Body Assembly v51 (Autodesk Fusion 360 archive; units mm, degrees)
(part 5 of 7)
sketch "Sketch36" plane through (0, 0, 68.45) normal (0, 0, 1) x axis (-1, 0, 0)
  line L1 (-90.9149, 154.35) -> (-90.9149, 141.35)
  line L2 (-88.4149, 157.35) -> (-90.9149, 154.35)
  line L3 (-85.2649, 157.35) -> (-88.4149, 157.35)
  line L4 (-82.7649, 154.35) -> (-85.2649, 157.35)
  line L5 (-82.7649, 141.35) -> (-82.7649, 154.35)
  line L6 (-90.9149, 141.35) -> (-82.7649, 141.35)
  line L7 (-93.1899, 97.475) -> (-80.4899, 97.475)
  line L8 (-93.1899, 118.675) -> (-93.1899, 97.475)
  line L9 (-80.4899, 118.675) -> (-93.1899, 118.675)
  line L10 (-80.4899, 97.475) -> (-80.4899, 118.675)
  line L11 (-116.1, 79.5) -> (-116.1, 158.6)
  line L12 (31.35, 79.5) -> (-116.1, 79.5)
  line L13 (31.35, 158.6) -> (31.35, 79.5)
  line L14 (-84.35, 190.35) -> (-0.4, 190.35)
  line L15 (-93.9399, 38.65) -> (-79.7399, 38.65)
  line L16 (-93.9399, 61.85) -> (-93.9399, 38.65)
  line L17 (-79.7399, 61.85) -> (-93.9399, 61.85)
  line L18 (-79.7399, 38.65) -> (-79.7399, 61.85)
  line L19 (-116.1, 0.4) -> (-116.1, 79.5)
  line L20 (-0.4, -31.35) -> (-84.35, -31.35)
  line L21 (31.35, 79.5) -> (31.35, 0.4)
  line L22 (-116.1, 79.5) -> (31.35, 79.5)
  line L23 (-79.99, 14.95) -> (-84.65, 14.95)
  line L24 (-79.99, 4.05) -> (-79.99, 14.95)
  line L25 (-84.65, 4.05) -> (-79.99, 4.05)
  line L26 (-84.65, 14.95) -> (-84.65, 4.05)
  line L27 (-79.99, -8.05) -> (-84.65, -8.05)
  line L28 (-79.99, -18.95) -> (-79.99, -8.05)
  line L29 (-84.65, -18.95) -> (-79.99, -18.95)
  line L30 (-84.65, -8.05) -> (-84.65, -18.95)
  line L31 (-68.5771, 14.95) -> (-73.2371, 14.95)
  line L32 (-68.5771, 4.05) -> (-68.5771, 14.95)
  line L33 (-73.2371, 4.05) -> (-68.5771, 4.05)
  line L34 (-73.2371, 14.95) -> (-73.2371, 4.05)
  line L35 (-68.5771, -8.05) -> (-73.2371, -8.05)
  line L36 (-68.5771, -18.95) -> (-68.5771, -8.05)
  line L37 (-73.2371, -18.95) -> (-68.5771, -18.95)
  line L38 (-73.2371, -8.05) -> (-73.2371, -18.95)
  line L39 (-57.1643, 14.95) -> (-61.8243, 14.95)
  line L40 (-57.1643, 4.05) -> (-57.1643, 14.95)
  line L41 (-61.8243, 4.05) -> (-57.1643, 4.05)
  line L42 (-61.8243, 14.95) -> (-61.8243, 4.05)
  line L43 (-57.1643, -8.05) -> (-61.8243, -8.05)
  line L44 (-57.1643, -18.95) -> (-57.1643, -8.05)
  line L45 (-61.8243, -18.95) -> (-57.1643, -18.95)
  line L46 (-61.8243, -8.05) -> (-61.8243, -18.95)
  line L47 (-45.7514, 14.95) -> (-50.4114, 14.95)
  line L48 (-45.7514, 4.05) -> (-45.7514, 14.95)
  line L49 (-50.4114, 4.05) -> (-45.7514, 4.05)
  line L50 (-50.4114, 14.95) -> (-50.4114, 4.05)
  line L51 (-45.7514, -8.05) -> (-50.4114, -8.05)
  line L52 (-45.7514, -18.95) -> (-45.7514, -8.05)
  line L53 (-50.4114, -18.95) -> (-45.7514, -18.95)
  line L54 (-50.4114, -8.05) -> (-50.4114, -18.95)
  line L55 (-34.3386, 14.95) -> (-38.9986, 14.95)
  line L56 (-34.3386, 4.05) -> (-34.3386, 14.95)
  line L57 (-38.9986, 4.05) -> (-34.3386, 4.05)
  line L58 (-38.9986, 14.95) -> (-38.9986, 4.05)
  line L59 (-34.3386, -8.05) -> (-38.9986, -8.05)
  line L60 (-34.3386, -18.95) -> (-34.3386, -8.05)
  line L61 (-38.9986, -18.95) -> (-34.3386, -18.95)
  line L62 (-38.9986, -8.05) -> (-38.9986, -18.95)
  line L63 (-22.9257, 14.95) -> (-27.5857, 14.95)
  line L64 (-22.9257, 4.05) -> (-22.9257, 14.95)
  line L65 (-27.5857, 4.05) -> (-22.9257, 4.05)
  line L66 (-27.5857, 14.95) -> (-27.5857, 4.05)
  line L67 (-22.9257, -8.05) -> (-27.5857, -8.05)
  line L68 (-22.9257, -18.95) -> (-22.9257, -8.05)
  line L69 (-27.5857, -18.95) -> (-22.9257, -18.95)
  line L70 (-27.5857, -8.05) -> (-27.5857, -18.95)
  line L71 (-11.5129, 14.95) -> (-16.1729, 14.95)
  line L72 (-11.5129, 4.05) -> (-11.5129, 14.95)
  line L73 (-16.1729, 4.05) -> (-11.5129, 4.05)
  line L74 (-16.1729, 14.95) -> (-16.1729, 4.05)
  line L75 (-11.5129, -8.05) -> (-16.1729, -8.05)
  line L76 (-11.5129, -18.95) -> (-11.5129, -8.05)
  line L77 (-16.1729, -18.95) -> (-11.5129, -18.95)
  line L78 (-16.1729, -8.05) -> (-16.1729, -18.95)
  line L79 (-0.1, 14.95) -> (-4.76, 14.95)
  line L80 (-0.1, 4.05) -> (-0.1, 14.95)
  line L81 (-4.76, 4.05) -> (-0.1, 4.05)
  line L82 (-4.76, 14.95) -> (-4.76, 4.05)
  line L83 (-0.1, -8.05) -> (-4.76, -8.05)
  line L84 (-0.1, -18.95) -> (-0.1, -8.05)
  line L85 (-4.76, -18.95) -> (-0.1, -18.95)
  line L86 (-4.76, -8.05) -> (-4.76, -18.95)
  circle C1 centre (-113.9, 107.8) radius 1.7
  circle C2 centre (20.495, 179.495) radius 1.7
  circle C3 centre (-105.245, 179.495) radius 1.7
  circle C4 centre (29.15, 107.8) radius 1.7
  arc A1 centre (-0.4, 158.6) radius 31.75 clockwise from (-0.4, 190.35) to (31.35, 158.6)
  arc A2 centre (-84.35, 158.6) radius 31.75 clockwise from (-116.1, 158.6) to (-84.35, 190.35)
  circle C5 centre (-105.245, -20.495) radius 1.7
  circle C6 centre (29.15, 51.2) radius 1.7
  circle C7 centre (20.495, -20.495) radius 1.7
  circle C8 centre (-113.9, 51.2) radius 1.7
  arc A3 centre (-84.35, 0.4) radius 31.75 clockwise from (-84.35, -31.35) to (-116.1, 0.4)
  arc A4 centre (-0.4, 0.4) radius 31.75 clockwise from (31.35, 0.4) to (-0.4, -31.35)
extrude "Extrude1" cut sketch "Sketch36" profile of L7 L8 L9 L10 L15 L16 L17 L18 along normal blind 38.1
extrude "Extrude2" add of existing geometry blind 2.7432
extrude "Extrude53" new body of existing geometry blind 6.35
extrude "Extrude3" add of existing geometry blind 1.075
extrude "Extrude55" new body of existing geometry blind 6.35
extrude "Extrude57" add of existing geometry blind 22.86
extrude "Extrude56" add of existing geometry blind 15.24
combine "Combine3"
offset_faces "OffsetFaces1" distance -2
chamfer "Chamfer1" distance 3.175
extrude "Extrude4" add of existing geometry blind 6.35
extrude "Extrude5" add of existing geometry blind 6.35
extrude "Extrude6" add of existing geometry blind 15.4432
extrude "Extrude7" add of existing geometry blind 13.7668
extrude "Extrude8" add of existing geometry blind 13.7668
extrude "Extrude9" add of existing geometry blind 15.4432
extrude "Extrude10" cut of existing geometry blind -6.35
extrude "Extrude12" add of existing geometry blind 27.2288
extrude "Extrude13" add of existing geometry blind 25.5524
component_from_bodies "Body->Comp2"
copy_paste "CutPaste1"
copy_paste "CutPaste7"
sketch "Sketch37" plane through (-44.05, 0, 0) normal (-1, 0, 0) x axis (0, -1, 0)
  line L1 (158.5956, -1.65) -> (0.4044, -1.65)
  line L2 (158.5956, 62.1) -> (158.5956, -1.65)
  line L3 (0.4044, 62.1) -> (158.5956, 62.1)
  line L4 (0.4044, -1.65) -> (0.4044, 62.1)
  line L5 (153.8331, 3.1125) -> (5.1669, 3.1125)
  line L6 (153.8331, 57.3375) -> (153.8331, 3.1125)
  line L7 (5.1669, 57.3375) -> (153.8331, 57.3375)
  line L8 (5.1669, 3.1125) -> (5.1669, 57.3375)
  line L9 (109.775, 57.3375) -> (49.225, 57.3375)
  line L10 (109.775, 46.3849) -> (109.775, 57.3375)
  line L11 (49.225, 46.3849) -> (109.775, 46.3849)
  line L12 (49.225, 57.3375) -> (49.225, 46.3849)
  line L13 (109.775, 3.1125) -> (49.225, 3.1125)
  line L14 (109.775, 12.875) -> (109.775, 3.1125)
  line L15 (49.225, 12.875) -> (109.775, 12.875)
  line L16 (49.225, 3.1125) -> (49.225, 12.875)
  line L17 (44.4625, -1.65) -> (44.4625, 17.6375)
  line L18 (114.5375, -1.65) -> (44.4625, -1.65)
  line L19 (114.5375, 17.6375) -> (114.5375, -1.65)
  line L20 (44.4625, 17.6375) -> (114.5375, 17.6375)
  line L21 (44.4625, 62.1) -> (44.4625, 41.6224)
  line L22 (114.5375, 62.1) -> (44.4625, 62.1)
  line L23 (114.5375, 41.6224) -> (114.5375, 62.1)
  line L24 (44.4625, 41.6224) -> (114.5375, 41.6224)
  line L25 (5.1669, 41.6224) -> (44.4625, 41.6224)
  line L26 (5.1669, 17.6375) -> (44.4625, 17.6375)
  line L27 (79.5, -1.65) -> (79.5, 62.1)
  line L28 (44.4625, 17.6375) -> (44.4625, 41.6224)
  line L29 (5.1669, 41.6224) -> (44.4625, 17.6375)
  line L30 (79.5, 41.6224) -> (44.4625, 17.6375)
  line L31 (44.4625, 57.3375) -> (5.1669, 41.6224)
  line L32 (5.1669, 3.1125) -> (44.4625, 17.6375)
  circle C1 centre (50.925, 11.175) radius 1.7
  circle C2 centre (69.975, 48.0849) radius 1.7
  circle C3 centre (50.925, 48.0849) radius 1.7
  circle C4 centre (69.975, 11.175) radius 1.7
  circle C5 centre (89.025, 11.175) radius 1.7
  circle C6 centre (108.075, 48.0849) radius 1.7
  circle C7 centre (89.025, 48.0849) radius 1.7
  circle C8 centre (108.075, 11.175) radius 1.7
  circle C9 centre (50.925, 48.0849) radius 2.75
  circle C10 centre (108.075, 48.0849) radius 2.75
  circle C11 centre (108.075, 11.175) radius 2.75
  circle C12 centre (50.925, 11.175) radius 2.75
  circle C13 centre (44.4625, 3.1125) radius 8.55
  circle C14 centre (5.1669, 3.1125) radius 8.55
  circle C15 centre (44.4625, 57.3375) radius 8.55
  circle C16 centre (5.1669, 57.3375) radius 8.55
  point P18 (49.225, 57.3375)
  point P22 (49.225, 3.1125)
  point P38 (5.1669, 41.6224)
  point P39 (5.1669, 17.6375)
  point P40 (79.5, 62.1)
  point P41 (79.5, -1.65)
  point P42 (79.5, 41.6224)
  point P43 (44.4625, 57.3375)
  point P44 (44.4625, 3.1125)
  point P14 (5.1669, 3.1125)
  point P45 (5.1669, 3.1125)
  point P46 (44.4625, 57.3375)
  point P17 (5.1669, 57.3375)
  point P47 (5.1669, 57.3375)
  horizontal L9
  vertical L10
  horizontal L11
  vertical L12
  coincident L7 P18
  horizontal L13
  vertical L14
  horizontal L15
  vertical L16
  coincident L5 P22
  coincident L8 P38
  perpendicular L8 L25
  coincident L8 P39
  perpendicular L8 L26
  midpoint L3 P40
  midpoint L18 P41
  midpoint L24 P42
  coincident L21 P43
  coincident L7 P43
  coincident L17 P44
  coincident L5 P44
  coincident P14 P45
  coincident P43 P46
  coincident P17 P47
  tangent C3 L11
  tangent C3 L12
  tangent C1 L16
  tangent C1 L15
  tangent C8 L14
  tangent C6 L10
  dimension "d404" = -4.7625
  dimension "d405" = 4.7625
  dimension "d406" = -4.7625
  dimension "d409" diameter C15 = 17.1 (= "threadedinsertdiam + 0.5 in")
  dimension "d410" diameter C13 = 17.1 (= "d409")
  dimension "d411" diameter C14 = 17.1 (= "d409")
  dimension "d412" diameter C16 = 17.1 (= "d409")
split "Split3"
extrude "Extrude14" cut sketch "Sketch37" profile of L5 L7 L8 L17 L20 L21 L24 L25 L26 L27 L28 L29 L30 L31 L32 C13 C14 C15 C16 against normal blind 7.62
extrude "Extrude58" new body of existing geometry blind -2.3813 (= "( -0.1875 / 2 ) * 1 in")
extrude "Extrude60" add of existing geometry blind 30.48
combine "Combine4"
web "Web1" Thickness 4.7625
delete_face "DeleteFace4"
delete_face "DeleteFace5"
fillet "Fillet3" radius 1.5875 (= "( 1 / 16 ) * 1 in")
hole "Hole1" HoleDepth 10.0076 HoleDiameter 4.4 (= "threadedinsertdiam") TipAngle 180
extrude "Extrude15" add sketch "Sketch37" profile of L1 L3 L4 L18 L22 C13 C14 C15 C16 against normal blind 6.35
fillet "Fillet5" radius 6.35
mirror "Mirror1" mirrorStitchTolerance 0.1016
remove_body "RemoveBody6"
remove_body "RemoveBody7"
mirror "Mirror2" mirrorStitchTolerance 0.1016
sketch "Sketch38" plane through (128.8, 0, 0) normal (1, 0, 0) x axis (0, 1, 0)
  line L1 (-25.9568, 62.1) -> (-131.375, 62.1)
  line L2 (-25.9568, 64.7303) -> (-25.9568, 62.1)
  line L3 (-131.375, 64.7303) -> (-25.9568, 64.7303)
  line L4 (-131.375, 62.1) -> (-131.375, 64.7303)
  line L5 (-140.5403, 36.2986) -> (-119.3333, 23.3545)
  line L6 (-118.5063, 39.2411) -> (-139.7132, 39.2411)
  line L7 (-116.9188, 24.7095) -> (-116.9188, 37.6536)
  line L8 (-114.5375, 45.5911) -> (-114.5375, 47.3251)
  line L9 (-133.2212, 44.0036) -> (-116.125, 44.0036)
  line L10 (-122.3147, 51.6626) -> (-133.8107, 47.0651)
  line L11 (-153.8331, 36.0038) -> (-153.8331, 21.6063)
  line L12 (-127.8303, 22.9613) -> (-151.4185, 37.3588)
  line L13 (-152.2456, 20.0188) -> (-128.6574, 20.0188)
  line L14 (-112.1563, 40.0349) -> (-112.1563, 25.1639)
  line L15 (-88.845, 41.6224) -> (-110.5688, 41.6224)
  line L16 (-109.672, 23.8539) -> (-87.9482, 38.7249)
  line L17 (-153.8331, 13.6688) -> (-153.8331, 13.1249)
  line L18 (-136.7214, 15.2563) -> (-152.2456, 15.2563)
  line L19 (-145.909, 8.5803) -> (-136.171, 12.1797)
  line L20 (-84.3655, 35.406) -> (-106.0893, 20.535)
  line L21 (-81.8812, 19.225) -> (-81.8813, 34.096)
  line L22 (-105.1925, 17.6375) -> (-83.4688, 17.6375)
  line L23 (-129.195, 57.3375) -> (-143.8207, 57.3375)
  line L24 (-151.6561, 45.0576) -> (-128.6056, 54.276)
  line L25 (-153.8331, 47.3251) -> (-153.8331, 46.5316)
  line L26 (-138.0913, 3.1125) -> (-124.5499, 3.1125)
  line L27 (-116.6477, 14.3188) -> (-138.6417, 6.189)
  line L28 (-34.4501, 3.1125) -> (-20.9087, 3.1125)
  line L29 (-20.3583, 6.189) -> (-42.3523, 14.3188)
  line L30 (-15.1793, 57.3375) -> (-29.805, 57.3375)
  line L31 (-5.1669, 46.5316) -> (-5.1669, 47.3251)
  line L32 (-30.3944, 54.276) -> (-7.3439, 45.0576)
  line L33 (-52.9107, 20.535) -> (-74.6345, 35.406)
  line L34 (-75.5312, 17.6375) -> (-53.8075, 17.6375)
  line L35 (-77.1188, 34.096) -> (-77.1188, 19.225)
  line L36 (-0.4044, 47.4117) -> (-0.4044, 13.0383)
  line L37 (-34.5367, 62.1) -> (-15.0927, 62.1)
  line L38 (-104.6117, 62.1) -> (-54.3883, 62.1)
  line L39 (-143.9073, 62.1) -> (-124.4633, 62.1)
  line L40 (-158.5956, 13.0383) -> (-158.5956, 47.4117)
  line L41 (-124.4633, -1.65) -> (-143.9073, -1.65)
  line L42 (-54.3883, -1.65) -> (-104.6117, -1.65)
  line L43 (-15.0927, -1.65) -> (-34.5367, -1.65)
  line L44 (-22.829, 12.1797) -> (-13.091, 8.5803)
  line L45 (-6.7544, 15.2563) -> (-22.2786, 15.2563)
  line L46 (-5.1669, 13.1249) -> (-5.1669, 13.6688)
  line L47 (-71.0518, 38.7249) -> (-49.328, 23.8539)
  line L48 (-48.4312, 41.6224) -> (-70.155, 41.6224)
  line L49 (-46.8438, 25.1639) -> (-46.8437, 40.0349)
  line L50 (-5.1669, 21.6063) -> (-5.1669, 36.0038)
  line L51 (-30.3426, 20.0188) -> (-6.7544, 20.0188)
  line L52 (-7.5815, 37.3588) -> (-31.1697, 22.9613)
  line L53 (-25.1893, 47.0651) -> (-36.6853, 51.6626)
  line L54 (-42.875, 44.0036) -> (-25.7788, 44.0036)
  line L55 (-44.4625, 47.3251) -> (-44.4625, 45.5911)
  line L56 (-39.6667, 23.3545) -> (-18.4597, 36.2986)
  line L57 (-42.0812, 37.6536) -> (-42.0812, 24.7095)
  line L58 (-19.2868, 39.2411) -> (-40.4937, 39.2411)
  circle C1 centre (-108.075, 48.0849) radius 1.7
  circle C2 centre (-89.025, 48.0849) radius 1.7
  arc A1 centre (-139.7132, 37.6536) radius 1.5875 clockwise from (-140.5403, 36.2986) to (-139.7132, 39.2411)
  arc A2 centre (-118.5063, 37.6536) radius 1.5875 clockwise from (-118.5063, 39.2411) to (-116.9188, 37.6536)
  arc A3 centre (-118.5063, 24.7095) radius 1.5875 clockwise from (-116.9188, 24.7095) to (-119.3333, 23.3545)
  arc A4 centre (-114.5375, 57.3375) radius 8.55 clockwise from (-115.8764, 48.893) to (-120.5996, 51.3081)
  arc A5 centre (-116.125, 47.3251) radius 1.5875 clockwise from (-115.8764, 48.893) to (-114.5375, 47.3251)
  arc A6 centre (-116.125, 45.5911) radius 1.5875 clockwise from (-114.5375, 45.5911) to (-116.125, 44.0036)
  arc A7 centre (-133.2212, 45.5911) radius 1.5875 clockwise from (-133.2212, 44.0036) to (-133.8107, 47.0651)
  arc A8 centre (-121.7252, 50.1886) radius 1.5875 clockwise from (-122.3147, 51.6626) to (-120.5996, 51.3081)
  arc A9 centre (-152.2456, 36.0038) radius 1.5875 clockwise from (-153.8331, 36.0038) to (-151.4185, 37.3588)
  arc A10 centre (-128.6574, 21.6063) radius 1.5875 clockwise from (-127.8303, 22.9613) to (-128.6574, 20.0188)
  arc A11 centre (-152.2456, 21.6063) radius 1.5875 clockwise from (-152.2456, 20.0188) to (-153.8331, 21.6063)
  arc A12 centre (-110.5688, 25.1639) radius 1.5875 clockwise from (-109.672, 23.8539) to (-112.1563, 25.1639)
  arc A13 centre (-110.5688, 40.0349) radius 1.5875 clockwise from (-112.1563, 40.0349) to (-110.5688, 41.6224)
  arc A14 centre (-88.845, 40.0349) radius 1.5875 clockwise from (-88.845, 41.6224) to (-87.9482, 38.7249)
  circle C3 centre (-108.075, 11.175) radius 1.7
  circle C4 centre (-89.025, 11.175) radius 1.7
  arc A15 centre (-153.8331, 3.1125) radius 8.55 clockwise from (-152.4942, 11.557) to (-147.6141, 8.9799)
  arc A16 centre (-152.2456, 13.1249) radius 1.5875 clockwise from (-152.4942, 11.557) to (-153.8331, 13.1249)
  arc A17 centre (-152.2456, 13.6688) radius 1.5875 clockwise from (-153.8331, 13.6688) to (-152.2456, 15.2563)
  arc A18 centre (-136.7214, 13.6688) radius 1.5875 clockwise from (-136.7214, 15.2563) to (-136.171, 12.1797)
  arc A19 centre (-146.4594, 10.0693) radius 1.5875 clockwise from (-145.909, 8.5803) to (-147.6141, 8.9799)
  arc A20 centre (-83.4688, 34.096) radius 1.5875 clockwise from (-84.3655, 35.406) to (-81.8813, 34.096)
  arc A21 centre (-83.4688, 19.225) radius 1.5875 clockwise from (-81.8812, 19.225) to (-83.4688, 17.6375)
  arc A22 centre (-105.1925, 19.225) radius 1.5875 clockwise from (-105.1925, 17.6375) to (-106.0893, 20.535)
  arc A23 centre (-129.195, 55.75) radius 1.5875 clockwise from (-129.195, 57.3375) to (-128.6056, 54.276)
  arc A24 centre (-152.2456, 46.5316) radius 1.5875 clockwise from (-151.6561, 45.0576) to (-153.8331, 46.5316)
  arc A25 centre (-152.2456, 47.3251) radius 1.5875 clockwise from (-153.8331, 47.3251) to (-152.4942, 48.893)
  arc A26 centre (-153.8331, 57.3375) radius 8.55 clockwise from (-145.3886, 55.9986) to (-152.4942, 48.893)
  arc A27 centre (-143.8207, 55.75) radius 1.5875 clockwise from (-145.3886, 55.9986) to (-143.8207, 57.3375)
  arc A28 centre (-138.0913, 4.7) radius 1.5875 clockwise from (-138.0913, 3.1125) to (-138.6417, 6.189)
  arc A29 centre (-116.0973, 12.8297) radius 1.5875 clockwise from (-116.6477, 14.3188) to (-114.5375, 13.1249)
  arc A30 centre (-116.125, 13.1249) radius 1.5875 clockwise from (-114.5375, 13.1249) to (-115.8764, 11.557)
  arc A31 centre (-114.5375, 3.1125) radius 8.55 clockwise from (-122.982, 4.4514) to (-115.8764, 11.557)
  arc A32 centre (-124.5499, 4.7) radius 1.5875 clockwise from (-122.982, 4.4514) to (-124.5499, 3.1125)
  circle C5 centre (-114.5375, 3.1125) radius 2.2
  circle C6 centre (-153.8331, 57.3375) radius 2.2
  circle C7 centre (-114.5375, 57.3375) radius 2.2
  circle C8 centre (-153.8331, 3.1125) radius 2.2
  circle C9 centre (-5.1669, 3.1125) radius 2.2
  circle C10 centre (-44.4625, 57.3375) radius 2.2
  circle C11 centre (-5.1669, 57.3375) radius 2.2
  circle C12 centre (-44.4625, 3.1125) radius 2.2
  arc A33 centre (-34.4501, 4.7) radius 1.5875 clockwise from (-34.4501, 3.1125) to (-36.018, 4.4514)
  arc A34 centre (-44.4625, 3.1125) radius 8.55 clockwise from (-43.1236, 11.557) to (-36.018, 4.4514)
  arc A35 centre (-42.875, 13.1249) radius 1.5875 clockwise from (-43.1236, 11.557) to (-44.4625, 13.1249)
  arc A36 centre (-42.9027, 12.8297) radius 1.5875 clockwise from (-44.4625, 13.1249) to (-42.3523, 14.3188)
  arc A37 centre (-20.9087, 4.7) radius 1.5875 clockwise from (-20.3583, 6.189) to (-20.9087, 3.1125)
  arc A38 centre (-15.1793, 55.75) radius 1.5875 clockwise from (-15.1793, 57.3375) to (-13.6114, 55.9986)
  arc A39 centre (-5.1669, 57.3375) radius 8.55 clockwise from (-6.5058, 48.893) to (-13.6114, 55.9986)
  arc A40 centre (-6.7544, 47.3251) radius 1.5875 clockwise from (-6.5058, 48.893) to (-5.1669, 47.3251)
  arc A41 centre (-6.7544, 46.5316) radius 1.5875 clockwise from (-5.1669, 46.5316) to (-7.3439, 45.0576)
  arc A42 centre (-29.805, 55.75) radius 1.5875 clockwise from (-30.3944, 54.276) to (-29.805, 57.3375)
  arc A43 centre (-53.8075, 19.225) radius 1.5875 clockwise from (-52.9107, 20.535) to (-53.8075, 17.6375)
  arc A44 centre (-75.5312, 19.225) radius 1.5875 clockwise from (-75.5312, 17.6375) to (-77.1188, 19.225)
  arc A45 centre (-75.5312, 34.096) radius 1.5875 clockwise from (-77.1188, 34.096) to (-74.6345, 35.406)
  arc A46 centre (-5.1669, 3.1125) radius 8.55 clockwise from (1.2097, 8.8082) to (-10.8626, -3.2641)
  arc A47 centre (5.9456, 13.0383) radius 6.35 clockwise from (1.2097, 8.8082) to (-0.4044, 13.0383)
  arc A48 centre (5.9456, 47.4117) radius 6.35 clockwise from (-0.4044, 47.4117) to (1.2097, 51.6418)
  arc A49 centre (-5.1669, 57.3375) radius 8.55 clockwise from (-10.8626, 63.7141) to (1.2097, 51.6418)
  arc A50 centre (-15.0927, 68.45) radius 6.35 clockwise from (-10.8626, 63.7141) to (-15.0927, 62.1)
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extrude "Extrude1" cut sketch "Sketch38" against normal blind 304.8
sketch "Sketch39" plane through (-44.05, 0, 0) normal (-1, 0, 0) x axis (0, -1, 0)
  line L1 (119.3333, 23.3545) -> (140.5403, 36.2986)
  line L2 (116.9188, 37.6536) -> (116.9188, 24.7095)
  line L3 (139.7132, 39.2411) -> (118.5063, 39.2411)
  line L4 (133.8107, 47.0651) -> (122.3147, 51.6626)
  line L5 (116.125, 44.0036) -> (133.2212, 44.0036)
  line L6 (114.5375, 47.3251) -> (114.5375, 45.5911)
  line L7 (153.8331, 21.6063) -> (153.8331, 36.0038)
  line L8 (128.6574, 20.0188) -> (152.2456, 20.0188)
  line L9 (151.4185, 37.3588) -> (127.8303, 22.9613)
  line L10 (87.9482, 38.7249) -> (109.672, 23.8539)
  line L11 (110.5688, 41.6224) -> (88.845, 41.6224)
  line L12 (112.1563, 25.1639) -> (112.1563, 40.0349)
  line L13 (136.171, 12.1797) -> (145.909, 8.5803)
  line L14 (152.2456, 15.2563) -> (136.7214, 15.2563)
  line L15 (153.8331, 13.1249) -> (153.8331, 13.6688)
  line L16 (106.0893, 20.535) -> (84.3655, 35.406)
  line L17 (83.4688, 17.6375) -> (105.1925, 17.6375)
  line L18 (81.8812, 34.096) -> (81.8813, 19.225)
  line L19 (143.8207, 57.3375) -> (129.195, 57.3375)
  line L20 (153.8331, 46.5316) -> (153.8331, 47.3251)
  line L21 (128.6056, 54.276) -> (151.6561, 45.0576)
  line L22 (124.5499, 3.1125) -> (138.0913, 3.1125)
  line L23 (138.6417, 6.189) -> (116.6477, 14.3188)
  line L24 (20.9087, 3.1125) -> (34.4501, 3.1125)
  line L25 (42.3523, 14.3188) -> (20.3583, 6.189)
  line L26 (29.805, 57.3375) -> (15.1793, 57.3375)
  line L27 (7.3439, 45.0576) -> (30.3944, 54.276)
  line L28 (5.1669, 47.3251) -> (5.1669, 46.5316)
  line L29 (74.6345, 35.406) -> (52.9107, 20.535)
  line L30 (77.1188, 19.225) -> (77.1188, 34.096)
  line L31 (53.8075, 17.6375) -> (75.5312, 17.6375)
  line L32 (34.5367, -1.65) -> (15.0927, -1.65)
  line L33 (104.6117, -1.65) -> (54.3883, -1.65)
  line L34 (143.9073, -1.65) -> (124.4633, -1.65)
  line L35 (158.5956, 47.4117) -> (158.5956, 13.0383)
  line L36 (124.4633, 62.1) -> (143.9073, 62.1)
  line L37 (54.3883, 62.1) -> (104.6117, 62.1)
  line L38 (15.0927, 62.1) -> (34.5367, 62.1)
  line L39 (0.4044, 13.0383) -> (0.4044, 47.4117)
  line L40 (5.1669, 13.6688) -> (5.1669, 13.1249)
  line L41 (22.2786, 15.2563) -> (6.7544, 15.2563)
  line L42 (13.091, 8.5803) -> (22.829, 12.1797)
  line L43 (46.8437, 40.0349) -> (46.8437, 25.1639)
  line L44 (70.155, 41.6224) -> (48.4312, 41.6224)
  line L45 (49.328, 23.8539) -> (71.0518, 38.7249)
  line L46 (5.1669, 36.0038) -> (5.1669, 21.6063)
  line L47 (31.1697, 22.9613) -> (7.5815, 37.3588)
  line L48 (6.7544, 20.0188) -> (30.3426, 20.0188)
  line L49 (44.4625, 45.5911) -> (44.4625, 47.3251)
  line L50 (25.7788, 44.0036) -> (42.875, 44.0036)
  line L51 (36.6853, 51.6626) -> (25.1893, 47.0651)
  line L52 (18.4597, 36.2986) -> (39.6667, 23.3545)
  line L53 (40.4937, 39.2411) -> (19.2868, 39.2411)
  line L54 (42.0812, 24.7095) -> (42.0812, 37.6536)
  line L55 (136.6611, 46) -> (156.8611, 46)
  line L56 (136.6611, 62.1) -> (136.6611, 46)
  line L57 (156.8611, 46) -> (156.8611, 62.1)
  line L58 (136.6611, 62.1) -> (156.8611, 62.1)
  line L59 (169.3015, 46) -> (136.6611, 46)
  line L60 (169.3015, 68.2941) -> (169.3015, 46)
  line L61 (136.6611, 68.2941) -> (169.3015, 68.2941)
  line L62 (136.6611, 46) -> (136.6611, 68.2941)
  line L63 (153.8331, 3.1125) -> (153.8331, 57.3375)
  circle C1 centre (108.075, 48.0849) radius 1.7
  circle C2 centre (89.025, 48.0849) radius 1.7
  arc A1 centre (118.5063, 24.7095) radius 1.5875 clockwise from (119.3333, 23.3545) to (116.9188, 24.7095)
  arc A2 centre (118.5063, 37.6536) radius 1.5875 clockwise from (116.9188, 37.6536) to (118.5063, 39.2411)
  arc A3 centre (139.7132, 37.6536) radius 1.5875 clockwise from (139.7132, 39.2411) to (140.5403, 36.2986)
  arc A4 centre (114.5375, 57.3375) radius 8.55 clockwise from (120.5996, 51.3081) to (115.8764, 48.893)
  arc A5 centre (121.7252, 50.1886) radius 1.5875 clockwise from (120.5996, 51.3081) to (122.3147, 51.6626)
  arc A6 centre (133.2212, 45.5911) radius 1.5875 clockwise from (133.8107, 47.0651) to (133.2212, 44.0036)
  arc A7 centre (116.125, 45.5911) radius 1.5875 clockwise from (116.125, 44.0036) to (114.5375, 45.5911)
  arc A8 centre (116.125, 47.3251) radius 1.5875 clockwise from (114.5375, 47.3251) to (115.8764, 48.893)
  arc A9 centre (152.2456, 21.6063) radius 1.5875 clockwise from (153.8331, 21.6063) to (152.2456, 20.0188)
  arc A10 centre (128.6574, 21.6063) radius 1.5875 clockwise from (128.6574, 20.0188) to (127.8303, 22.9613)
  arc A11 centre (152.2456, 36.0038) radius 1.5875 clockwise from (151.4185, 37.3588) to (153.8331, 36.0038)
  arc A12 centre (110.5688, 25.1639) radius 1.5875 clockwise from (112.1563, 25.1639) to (109.672, 23.8539)
  arc A13 centre (88.845, 40.0349) radius 1.5875 clockwise from (87.9482, 38.7249) to (88.845, 41.6224)
  arc A14 centre (110.5688, 40.0349) radius 1.5875 clockwise from (110.5688, 41.6224) to (112.1563, 40.0349)
  circle C3 centre (108.075, 11.175) radius 1.7
  circle C4 centre (89.025, 11.175) radius 1.7
  arc A15 centre (153.8331, 3.1125) radius 8.55 clockwise from (147.6141, 8.9799) to (152.4942, 11.557)
  arc A16 centre (146.4594, 10.0693) radius 1.5875 clockwise from (147.6141, 8.9799) to (145.909, 8.5803)
  arc A17 centre (136.7214, 13.6688) radius 1.5875 clockwise from (136.171, 12.1797) to (136.7214, 15.2563)
  arc A18 centre (152.2456, 13.6688) radius 1.5875 clockwise from (152.2456, 15.2563) to (153.8331, 13.6688)
  arc A19 centre (152.2456, 13.1249) radius 1.5875 clockwise from (153.8331, 13.1249) to (152.4942, 11.557)
  arc A20 centre (105.1925, 19.225) radius 1.5875 clockwise from (106.0893, 20.535) to (105.1925, 17.6375)
  arc A21 centre (83.4688, 19.225) radius 1.5875 clockwise from (83.4688, 17.6375) to (81.8813, 19.225)
  arc A22 centre (83.4687, 34.096) radius 1.5875 clockwise from (81.8812, 34.096) to (84.3655, 35.406)
  arc A23 centre (143.8207, 55.75) radius 1.5875 clockwise from (143.8207, 57.3375) to (145.3886, 55.9986)
  arc A24 centre (153.8331, 57.3375) radius 8.55 clockwise from (152.4942, 48.893) to (145.3886, 55.9986)
  arc A25 centre (152.2456, 47.3251) radius 1.5875 clockwise from (152.4942, 48.893) to (153.8331, 47.3251)
  arc A26 centre (152.2456, 46.5316) radius 1.5875 clockwise from (153.8331, 46.5316) to (151.6561, 45.0576)
  arc A27 centre (129.195, 55.75) radius 1.5875 clockwise from (128.6056, 54.276) to (129.195, 57.3375)
  arc A28 centre (124.5499, 4.7) radius 1.5875 clockwise from (124.5499, 3.1125) to (122.982, 4.4514)
  arc A29 centre (114.5375, 3.1125) radius 8.55 clockwise from (115.8764, 11.557) to (122.982, 4.4514)
  arc A30 centre (116.125, 13.1249) radius 1.5875 clockwise from (115.8764, 11.557) to (114.5375, 13.1249)
  arc A31 centre (116.0973, 12.8297) radius 1.5875 clockwise from (114.5375, 13.1249) to (116.6477, 14.3188)
  arc A32 centre (138.0913, 4.7) radius 1.5875 clockwise from (138.6417, 6.189) to (138.0913, 3.1125)
  circle C5 centre (114.5375, 3.1125) radius 2.2
  circle C6 centre (153.8331, 57.3375) radius 2.2
  circle C7 centre (114.5375, 57.3375) radius 2.2
  circle C8 centre (153.8331, 3.1125) radius 2.2
  circle C9 centre (5.1669, 3.1125) radius 2.2
  circle C10 centre (44.4625, 57.3375) radius 2.2
  circle C11 centre (5.1669, 57.3375) radius 2.2
  circle C12 centre (44.4625, 3.1125) radius 2.2
  arc A33 centre (20.9087, 4.7) radius 1.5875 clockwise from (20.9087, 3.1125) to (20.3583, 6.189)
  arc A34 centre (42.9027, 12.8297) radius 1.5875 clockwise from (42.3523, 14.3188) to (44.4625, 13.1249)
  arc A35 centre (42.875, 13.1249) radius 1.5875 clockwise from (44.4625, 13.1249) to (43.1236, 11.557)
  arc A36 centre (44.4625, 3.1125) radius 8.55 clockwise from (36.018, 4.4514) to (43.1236, 11.557)
  arc A37 centre (34.4501, 4.7) radius 1.5875 clockwise from (36.018, 4.4514) to (34.4501, 3.1125)
  arc A38 centre (29.805, 55.75) radius 1.5875 clockwise from (29.805, 57.3375) to (30.3944, 54.276)
  arc A39 centre (6.7544, 46.5316) radius 1.5875 clockwise from (7.3439, 45.0576) to (5.1669, 46.5316)
  arc A40 centre (6.7544, 47.3251) radius 1.5875 clockwise from (5.1669, 47.3251) to (6.5058, 48.893)
  arc A41 centre (5.1669, 57.3375) radius 8.55 clockwise from (13.6114, 55.9986) to (6.5058, 48.893)
  arc A42 centre (15.1793, 55.75) radius 1.5875 clockwise from (13.6114, 55.9986) to (15.1793, 57.3375)
  arc A43 centre (75.5312, 34.096) radius 1.5875 clockwise from (74.6345, 35.406) to (77.1188, 34.096)
  arc A44 centre (75.5312, 19.225) radius 1.5875 clockwise from (77.1188, 19.225) to (75.5312, 17.6375)
  arc A45 centre (53.8075, 19.225) radius 1.5875 clockwise from (53.8075, 17.6375) to (52.9107, 20.535)
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  point P233 (136.6611, 46)
  point P236 (136.6611, 46)
  point P73 (153.8331, 57.3375)
  point P240 (153.8331, 57.3375)
  point P48 (153.8331, 3.1125)
  point P241 (153.8331, 3.1125)
  point P242 (153.8331, 37.45)
  horizontal L59
  vertical L60
  horizontal L61
  vertical L62
  coincident P233 P236
  coincident P73 P240
  coincident P48 P241
  coincident L63 P242
  dimension "d441" diameter = 4.4 (= "threadedinsertdiam")
  dimension "d442" = 6.35
extrude "Extrude16" cut sketch "Sketch39" against normal blind 20.32
delete_face "DeleteFace6"
delete_face "DeleteFace7"
delete_face "DeleteFace8"
delete_face "DeleteFace9"
extrude "Extrude17" add sketch "Sketch39" against normal blind 6.35
delete_face "DeleteFace10"
fillet "Fillet6" radius 1.5875 (= "( 1 / 16 ) * 1 in")
fillet "Fillet7" radius 6.35
hole "Hole2" HoleDepth 10.0076 HoleDiameter 4.4 (= "threadedinsertdiam") TipAngle 180
move_face "MoveFace3"
sketch "Sketch40" plane through (0, 0, 74.8) normal (0, 0, 1) x axis (-1, 0, 0)
  line L1 (-98.3649, 123.85) -> (-98.3649, 92.3)
  line L2 (-75.3149, 123.85) -> (-98.3649, 123.85)
  line L3 (-75.3149, 92.3) -> (-75.3149, 123.85)
  line L4 (-98.3649, 92.3) -> (-75.3149, 92.3)
  line L5 (-118.7303, 25.9568) -> (-118.7303, 131.375)
  line L6 (33.9803, 25.9568) -> (-118.7303, 25.9568)
  line L7 (33.9803, 131.375) -> (33.9803, 25.9568)
  line L8 (-118.7303, 131.375) -> (33.9803, 131.375)
  line L9 (-76.5649, 35.4818) -> (-76.5649, 65.025)
  line L10 (-97.1149, 35.4818) -> (-76.5649, 35.4818)
  line L11 (-97.1149, 65.025) -> (-97.1149, 35.4818)
  line L12 (-76.5649, 65.025) -> (-97.1149, 65.025)
  line L13 (-107.4375, 25.9568) -> (-118.7303, 25.9568)
  line L14 (-118.7303, 131.375) -> (-107.4375, 131.375)
  line L15 (-118.7303, 25.9568) -> (-118.7303, 131.375)
  line L16 (22.6875, 25.9568) -> (33.9803, 25.9568)
  line L17 (22.6875, 131.375) -> (22.6875, 25.9568)
  line L18 (33.9803, 131.375) -> (22.6875, 131.375)
  line L19 (33.9803, 25.9568) -> (33.9803, 131.375)
  line L20 (-70.5524, 131.375) -> (-70.5524, 25.9568)
  line L21 (22.6875, 126.6125) -> (-70.5524, 126.6125)
  line L22 (22.6875, 30.7193) -> (-70.5524, 30.7193)
  line L23 (-47.2424, 126.6125) -> (-47.2424, 30.7193)
  line L24 (-23.9325, 30.7193) -> (-23.9325, 126.6125)
  line L25 (-0.6225, 126.6125) -> (-0.6225, 30.7193)
  line L26 (-70.5524, 54.6926) -> (-47.2424, 30.7193)
  line L27 (-47.2424, 78.6659) -> (-70.5524, 54.6926)
  line L28 (-70.5524, 102.6392) -> (-47.2424, 78.6659)
  line L29 (-47.2424, 126.6125) -> (-70.5524, 102.6392)
  line L30 (-47.2424, 54.6926) -> (-70.5524, 54.6926)
  line L31 (-47.2424, 102.6392) -> (-70.5524, 102.6392)
  line L32 (-70.5524, 78.6659) -> (-47.2424, 78.6659)
  line L33 (-23.9325, 54.6926) -> (-47.2424, 30.7193)
  line L34 (-47.2424, 78.6659) -> (-23.9325, 54.6926)
  line L35 (-47.2424, 54.6926) -> (-23.9325, 54.6926)
  line L36 (-23.9325, 78.6659) -> (-47.2424, 78.6659)
  line L37 (-23.9325, 102.6392) -> (-47.2424, 78.6659)
  line L38 (-23.9325, 102.6392) -> (-47.2424, 126.6125)
  line L39 (-47.2424, 102.6392) -> (-23.9325, 102.6392)
  line L40 (-0.6225, 78.6659) -> (-23.9325, 54.6926)
  line L41 (-0.6225, 54.6926) -> (-23.9325, 54.6926)
  line L42 (-23.9325, 54.6926) -> (-0.6225, 30.7193)
  line L43 (22.6875, 54.6926) -> (-0.6225, 30.7193)
  line L44 (-0.6225, 54.6926) -> (22.6875, 54.6926)
  line L45 (-0.6225, 78.6659) -> (22.6875, 54.6926)
  line L46 (22.6875, 102.6392) -> (-0.6225, 78.6659)
  line L47 (-0.6225, 126.6125) -> (22.6875, 102.6392)
  line L48 (-23.9325, 102.6392) -> (-0.6225, 126.6125)
  line L49 (-23.9325, 102.6392) -> (-0.6225, 78.6659)
  line L50 (-0.6225, 102.6392) -> (22.6875, 102.6392)
  line L51 (-0.6225, 102.6392) -> (-23.9325, 102.6392)
  line L52 (-23.9325, 78.6659) -> (-0.6225, 78.6659)
  line L53 (22.6875, 78.6659) -> (-0.6225, 78.6659)
  circle C1 centre (29.15, 51.2) radius 1.7
  circle C2 centre (29.15, 107.8) radius 1.7
  circle C3 centre (-113.9, 107.8) radius 1.7
  circle C4 centre (-113.9, 51.2) radius 1.7
  point P20 (-107.4375, 131.375)
  point P7 (-118.7303, 25.9568)
  point P18 (-118.7303, 25.9568)
  point P24 (22.6875, 131.375)
  point P8 (33.9803, 25.9568)
  point P22 (33.9803, 25.9568)
  point P26 (-70.5524, 25.9568)
  point P27 (-70.5524, 131.375)
  point P28 (-70.5524, 126.6125)
  point P29 (22.6875, 126.6125)
  point P30 (-70.5524, 30.7193)
  point P31 (22.6875, 30.7193)
  point P32 (-47.2424, 30.7193)
  point P33 (-47.2424, 126.6125)
  point P34 (-23.9325, 126.6125)
  point P35 (-23.9325, 30.7193)
  point P36 (-0.6225, 30.7193)
  point P37 (-0.6225, 126.6125)
  point P38 (-70.5524, 54.6926)
  point P39 (-47.2424, 78.6659)
  point P40 (-70.5524, 102.6392)
  point P41 (-47.2424, 54.6926)
  point P42 (-47.2424, 102.6392)
  point P43 (-70.5524, 78.6659)
  point P44 (-23.9325, 54.6926)
  point P45 (-47.2424, 54.6926)
  point P46 (-23.9325, 78.6659)
  point P47 (-23.9325, 102.6392)
  point P48 (-47.2424, 102.6392)
  point P52 (-0.6225, 30.7193)
  point P56 (-0.6225, 126.6125)
  point P53 (22.6875, 54.6926)
  point P50 (-0.6225, 78.6659)
  point P55 (22.6875, 102.6392)
  point P54 (-0.6225, 54.6926)
  point P58 (-0.6225, 102.6392)
  point P49 (-23.9325, 54.6926)
  point P51 (-0.6225, 54.6926)
  point P57 (-23.9325, 102.6392)
  point P59 (-0.6225, 102.6392)
  point P60 (-0.6225, 78.6659)
  point P61 (-23.9325, 78.6659)
  point P62 (-0.6225, 78.6659)
  point P63 (22.6875, 78.6659)
  point P15 (29.15, 107.8)
  point P5 (-75.3149, 92.3)
  horizontal L13
  horizontal L14
  vertical L15
  coincident L8 P20
  coincident P7 P18
  horizontal L16
  vertical L17
  horizontal L18
  vertical L19
  coincident L8 P24
  coincident P8 P22
  coincident L6 P26
  coincident L8 P27
  perpendicular L8 L20
  coincident L20 P28
  coincident L17 P29
  perpendicular L17 L21
  coincident L20 P30
  coincident L17 P31
  perpendicular L17 L22
  coincident L22 P32
  coincident L21 P33
  perpendicular L21 L23
  coincident L21 P34
  coincident L22 P35
  perpendicular L22 L24
  coincident L22 P36
  coincident L21 P37
  perpendicular L21 L25
  coincident L20 P38
  coincident L23 P39
  coincident L20 P40
  coincident L23 P41
  perpendicular L23 L30
  coincident L23 P42
  perpendicular L23 L31
  coincident L20 P43
  perpendicular L20 L32
  coincident L24 P44
  coincident L23 P45
  perpendicular L23 L35
  midpoint L24 P46
  coincident L24 P47
  coincident L23 P48
  perpendicular L23 L39
  symmetric P32 L24 P52
  symmetric P33 L24 P56
  symmetric L24 P38 P53
  symmetric L24 P39 P50
  symmetric L24 P40 P55
  symmetric L24 P41 P54
  symmetric L24 P42 P58
  symmetric L24 P44 P49
  symmetric L24 P45 P51
  symmetric L24 P47 P57
  symmetric L24 P48 P59
  symmetric L24 P39 P60
  symmetric L24 P46 P61
  symmetric L24 P39 P62
  symmetric L24 P43 P63
  dimension "d455" distance P15 L17 = 6.4625 (= "( ( 3 / 16 ) * 1 in ) + ( m3screwdiam / 2 )")
  dimension "d456" distance P5 L20 = 4.7625 (= "( 3 / 16 ) * 1 in")
  dimension "d457" distance L6 L22 = 4.7625 (= "( 3 / 16 ) * 1 in")
  dimension "d458" distance L8 L21 = 4.7625 (= "( 3 / 16 ) * 1 in")
  dimension "d459" distance L20 L23 = 23.31 (= "3.6708627805633998 in / 4")
  dimension "d460" distance L20 L24 = 46.62 (= "3.6708627805633998 in / 2")
  dimension "d461" distance L20 L25 = 69.9299 (= "3.6708627805633998 in * 0.75")
  dimension "d462" distance P33 P39 = 47.9466 (= "3.7753228345999998 in / 2")
  dimension "d463" distance P30 P38 = 23.9733 (= "3.7753228345999998 in / 4")
  dimension "d464" distance P35 P44 = 23.9733 (= "3.7753228345999998 in / 4")
  dimension "d465" distance P28 P40 = 23.9733 (= "3.7753228345999998 in / 4")
  dimension "d466" distance P34 P47 = 23.9733 (= "3.7753228345999998 in / 4")
hole "Hole1" HoleDepth 10.0076 HoleDiameter 3.4 (= "m3screwdiam") TipAngle 180
extrude "Extrude2" cut sketch "Sketch40" profile of L17 L20 L21 L22 L23 L24 L25 L26 L27 L28 L29 L30 L31 L32 L33 L34 L35 L36 L37 L38 L39 L40 L41 L42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 against normal blind 30.48
web "Web1" Thickness 4.7625 (= "( 3 / 16 ) * 1 in") Depth 6.35
fillet "Fillet1" radius 1.5875 (= "( 1 / 16 ) * 1 in")
hole "Hole2" HoleDepth 10.0076 HoleDiameter 4.4 (= "threadedinsertdiam") TipAngle 180
offset_faces "OffsetFaces1" distance -0.5
offset_faces "OffsetFaces2" distance 0.5
position "Position26"
sketch "Sketch41" plane through (0, 0, 68.45) normal (0, 0, 1) x axis (-1, 0, 0)
  line L1 (-90.9149, 154.35) -> (-90.9149, 141.35)
  line L2 (-88.4149, 157.35) -> (-90.9149, 154.35)
  line L3 (-85.2649, 157.35) -> (-88.4149, 157.35)
  line L4 (-82.7649, 154.35) -> (-85.2649, 157.35)
  line L5 (-82.7649, 141.35) -> (-82.7649, 154.35)
  line L6 (-90.9149, 141.35) -> (-82.7649, 141.35)
  line L7 (-93.1899, 97.475) -> (-80.4899, 97.475)
  line L8 (-93.1899, 118.675) -> (-93.1899, 97.475)
  line L9 (-80.4899, 118.675) -> (-93.1899, 118.675)
  line L10 (-80.4899, 97.475) -> (-80.4899, 118.675)
  line L11 (-116.1, 79.5) -> (-116.1, 158.6)
  line L12 (31.35, 79.5) -> (-116.1, 79.5)
  line L13 (31.35, 158.6) -> (31.35, 79.5)
  line L14 (-84.35, 190.35) -> (-0.4, 190.35)
  circle C1 centre (-113.9, 107.8) radius 1.7
  circle C2 centre (20.495, 179.495) radius 1.7
  circle C3 centre (-105.245, 179.495) radius 1.7
  circle C4 centre (29.15, 107.8) radius 1.7
  arc A1 centre (-0.4, 158.6) radius 31.75 clockwise from (-0.4, 190.35) to (31.35, 158.6)
  arc A2 centre (-84.35, 158.6) radius 31.75 clockwise from (-116.1, 158.6) to (-84.35, 190.35)
  circle C5 centre (-140.4555, 194.1596) radius 1.7
  circle C6 centre (-140.4555, 194.1596) radius 4.875
  dimension "d481" diameter C5 = 3.4 (= "m3screwdiam")
  dimension "d482" = 3.175
extrude "Extrude61" new body sketch "Sketch41" profile of C5 C6 along normal blind 6.35
move "Move2"
align "Align20"
copy_paste_bodies "CopyPasteBodies21"
move "Move23"
copy_paste_bodies "CopyPasteBodies22"
move "Move24"
copy_paste_bodies "CopyPasteBodies23"
move "Move25"
align "Align21"
align "Align22"
align "Align23"
component_from_bodies "Body->Comp9"
copy_paste_bodies "CutPasteBodies1"
copy_paste_bodies "CopyPasteBodies1"
move "Move2"
align "Align1"
copy_paste_bodies "CopyPasteBodies24"
move "Move26"
copy_paste_bodies "CopyPasteBodies25"
move "Move27"
copy_paste_bodies "CopyPasteBodies26"
move "Move28"
copy_paste_bodies "CopyPasteBodies27"
move "Move29"
copy_paste_bodies "CopyPasteBodies28"
move "Move30"
copy_paste_bodies "CopyPasteBodies29"
move "Move31"
copy_paste_bodies "CopyPasteBodies30"
move "Move32"
align "Align24"
align "Align25"
align "Align26"
align "Align27"
align "Align28"
align "Align29"
align "Align30"
mirror "Mirror10" mirrorStitchTolerance 0.1016
align "Align31"
copy_paste_bodies "CopyPasteBodies31"
move "Move33"
align "Align32"
copy_paste_bodies "CutPasteBodies2"
copy_paste "CutPaste8"
copy_paste_bodies "CopyPasteBodies32"
move "Move34"
align "Align33"
copy_paste_bodies "CopyPasteBodies33"
move "Move35"
align "Align34"
copy_paste_bodies "CopyPasteBodies34"
move "Move36"
align "Align35"
copy_paste_bodies "CopyPasteBodies35"
move "Move37"
align "Align36"
copy_paste_bodies "CutPasteBodies3"
copy_paste_bodies "CutPasteBodies5"
as_built_joint "As-built2"
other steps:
base_feature "Base Feature1"
base_feature "Base Feature1"
base_feature "Base Feature1"
base_feature "Base Feature1"
base_feature "Base Feature1"
base_feature "Base Feature1"
base_feature "Base Feature1"
base_feature "Base Feature1"
base_feature "Base Feature1"
base_feature "Base Feature1"
base_feature "Base Feature1"
base_feature "Base Feature2"
base_feature "Base Feature2"
base_feature "Base Feature2"
base_feature "Base Feature2"
base_feature "Base Feature2"
base_feature "Base Feature2"
base_feature "Base Feature2"
base_feature "Base Feature2"
base_feature "Base Feature2"
base_feature "Base Feature2"
base_feature "Base Feature3"
base_feature "Base Feature1"
base_feature "Base Feature4"
base_feature "Base Feature5"
base_feature "Base Feature2"
base_feature "Base Feature1"
delete_face "DeleteFace2"
delete_face "DeleteFace3"
delete_face "DeleteFace4"
base_feature "Base Feature6"
base_feature "Base Feature1"
base_feature "Base Feature2"
base_feature "Base Feature3"
base_feature "Base Feature3"
base_feature "Base Feature4"
base_feature "Base Feature1"
base_feature "Base Feature2"
base_feature "Base Feature3"
base_feature "Base Feature4"
base_feature "Base Feature5"
base_feature "Base Feature6"
base_feature "Base Feature7"
base_feature "Base Feature8"
base_feature "Base Feature9"
base_feature "Base Feature10"
base_feature "Base Feature11"
base_feature "Base Feature12"
base_feature "Base Feature13"
base_feature "Base Feature14"
base_feature "Base Feature15"
base_feature "Base Feature16"
base_feature "Base Feature17"
base_feature "Base Feature18"
base_feature "Base Feature19"
base_feature "Base Feature20"
base_feature "Base Feature21"
base_feature "Base Feature22"
base_feature "Base Feature23"
base_feature "Base Feature24"
base_feature "Base Feature25"
base_feature "Base Feature26"
base_feature "Base Feature27"
base_feature "Base Feature28"
base_feature "Base Feature29"
base_feature "Base Feature30"
base_feature "Base Feature31"
base_feature "Base Feature32"
base_feature "Base Feature33"
base_feature "Base Feature34"
base_feature "Base Feature35"
create_component "CreateComponent1"
remove_instance "RemoveInstance1"
remove_instance "RemoveInstance2"
remove_instance "RemoveInstance3"
remove_instance "RemoveInstance4"
remove_instance "RemoveInstance5"
remove_instance "RemoveInstance6"
remove_instance "RemoveInstance7"
remove_instance "RemoveInstance8"
create_component "CreateComponent2"
remove_instance "RemoveInstance9"
remove_instance "RemoveInstance10"
remove_instance "RemoveInstance11"
create_component "CreateComponent3"
remove_instance "RemoveInstance12"
remove_instance "RemoveInstance13"
remove_instance "RemoveInstance14"
remove_instance "RemoveInstance15"
create_component "CreateComponent4"
remove_body "RemoveBody3"
remove_body "RemoveBody4"
create_component "CreateComponent5"
remove_body "RemoveBody5"
create_component "CreateComponent6"
remove_body "RemoveBody6"
remove_body "RemoveBody7"
remove_body "RemoveBody8"
create_component "CreateComponent7"
remove_body "RemoveBody9"
remove_body "RemoveBody10"
create_component "CreateComponent8"
create_component "CreateComponent9"
remove_instance "RemoveInstance16"
remove_instance "RemoveInstance17"
remove_instance "RemoveInstance18"
remove_instance "RemoveInstance19"
remove_instance "RemoveInstance20"
create_component "CreateComponent10"
create_component "CreateComponent1"
remove_body "RemoveBody1"
create_component "CreateComponent2"
remove_body "RemoveBody2"
remove_body "RemoveBody11"
remove_body "RemoveBody12"
remove_body "RemoveBody13"
remove_body "RemoveBody14"
remove_body "RemoveBody15"
remove_body "RemoveBody16"
remove_body "RemoveBody17"
remove_body "RemoveBody18"
remove_body "RemoveBody19"
remove_body "RemoveBody20"
remove_body "RemoveBody21"
remove_body "RemoveBody22"
remove_body "RemoveBody23"
remove_body "RemoveBody24"
remove_instance "RemoveInstance21"
create_component "CreateComponent1"
create_component "CreateComponent2"
create_component "CreateComponent11"
remove_body "RemoveBody25"
remove_body "RemoveBody26"
remove_body "RemoveBody27"
remove_body "RemoveBody28"
remove_body "RemoveBody29"
remove_instance "RemoveInstance22"
create_component "CreateComponent12"
remove_body "RemoveBody30"
remove_instance "RemoveInstance23"
create_component "CreateComponent1"
remove_body "RemoveBody1"
remove_body "RemoveBody2"
remove_instance "RemoveInstance1"
create_component "CreateComponent13"
remove_body "RemoveBody31"
remove_instance "RemoveInstance24"
remove_body "RemoveBody32"
remove_body "RemoveBody33"
remove_body "RemoveBody34"
create_component "CreateComponent14"
remove_body "RemoveBody35"
remove_instance "RemoveInstance25"
remove_body "RemoveBody36"
create_component "CreateComponent15"
remove_body "RemoveBody37"
remove_instance "RemoveInstance26"
remove_body "RemoveBody1"
remove_body "RemoveBody38"
remove_body "RemoveBody39"
create_component "CreateComponent2"
remove_body "RemoveBody5"
remove_instance "RemoveInstance2"
remove_instance "RemoveInstance27"
remove_body "RemoveBody40"
create_component "CreateComponent16"
remove_body "RemoveBody41"
remove_body "RemoveBody42"
remove_body "RemoveBody43"
remove_body "RemoveBody44"
remove_body "RemoveBody45"
remove_body "RemoveBody46"
remove_body "RemoveBody47"
remove_body "RemoveBody48"
remove_body "RemoveBody49"
remove_body "RemoveBody50"
remove_body "RemoveBody51"
remove_body "RemoveBody52"
remove_body "RemoveBody53"
remove_body "RemoveBody54"
remove_body "RemoveBody55"
remove_body "RemoveBody56"
remove_body "RemoveBody57"
remove_body "RemoveBody58"
remove_body "RemoveBody59"
remove_instance "RemoveInstance28"
remove_body "RemoveBody60"
remove_body "RemoveBody61"
remove_body "RemoveBody62"
remove_body "RemoveBody63"
remove_body "RemoveBody3"
remove_body "RemoveBody4"
remove_body "RemoveBody5"
remove_body "RemoveBody6"
remove_body "RemoveBody7"
remove_body "RemoveBody8"
remove_body "RemoveBody9"
remove_body "RemoveBody10"
remove_body "RemoveBody11"
remove_body "RemoveBody12"
remove_body "RemoveBody13"
remove_body "RemoveBody14"
remove_body "RemoveBody15"
remove_body "RemoveBody16"
remove_body "RemoveBody17"
remove_body "RemoveBody18"
remove_body "RemoveBody19"
remove_body "RemoveBody20"
remove_body "RemoveBody21"
remove_body "RemoveBody22"

design "Servo Actuator 2.0"
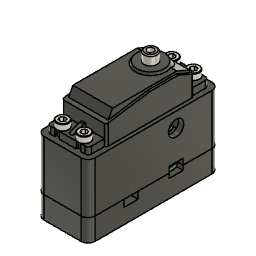
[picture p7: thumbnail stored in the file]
base_feature "Base Feature1"
base_feature "Base Feature1"
base_feature "Base Feature1"
base_feature "Base Feature1"
extrude "Extrude1" add of existing geometry blind 3.556
extrude "Extrude2" add of existing geometry blind 1
sketch "Sketch1" plane through (0, 0, 13.9918) normal (0, 0, -1) x axis (1, 0, 0)
  circle C1 centre (0, -10.25) radius 4
  circle C2 centre (0, -10.25) radius 8.7625
  dimension "d5" = 4.7625
extrude "Extrude1" new body sketch "Sketch1" along normal blind 5.675 (= "0.125 in + 2.5 mm")
extrude "Extrude3" add of existing geometry blind 3.175
combine "Combine1"
extrude "Extrude2" cut of existing geometry blind -4.7
sketch "Sketch2" plane through (0, 0, 24.9956) normal (0, 0, 1) x axis (-1, 0, 0)
  line L1 (0.8395, -12.0586) -> (1.9866, -10.4203)
  line L2 (-1.9866, -10.0797) -> (0.8395, -12.0586)
  line L3 (-0.8395, -8.4414) -> (-1.9866, -10.0797)
  line L4 (1.9866, -10.4203) -> (-0.8395, -8.4414)
  line L5 (-1.9866, -10.0797) -> (-0.8395, -8.4414)
  line L6 (0.8395, -12.0586) -> (-1.9866, -10.0797)
  line L7 (1.9866, -10.4203) -> (0.8395, -12.0586)
  line L8 (-0.8395, -8.4414) -> (1.9866, -10.4203)
  circle C1 centre (0, -10.25) radius 4
split "Split1"
copy_paste_bodies "CutPasteBodies1"
copy_paste_bodies "CutPasteBodies1"
component_from_bodies "Body->Comp1"
extrude "Extrude3" new body of existing geometry blind 2.5
delete_face "DeleteFace1"
component_from_bodies "Body->Comp1"
copy_paste "CutPaste1"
